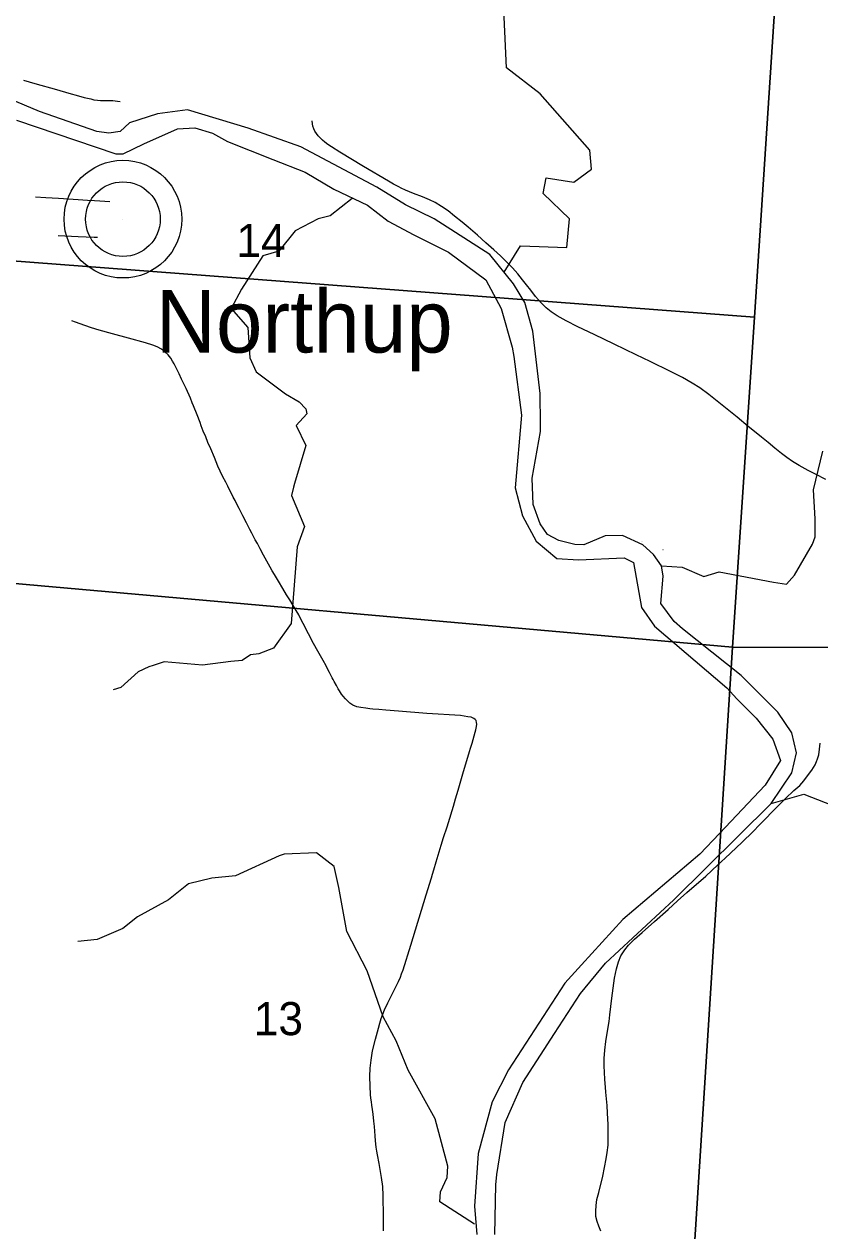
# Model space of a CAD drawing. Extents: x 0 to 34, y 0 to 22.
# Drawn here: x 24.476 to 25.483, y 16.271 to 17.797 of the extents above; entities that cross this region are included whole.
import ezdxf

# ---------------------------------------------------------------- set-up
doc = ezdxf.new("R2010")
doc.units = 0
for name, color, linetype in [('GM_X_County_Road', 7, 'Continuous'), ('GM_X_Major_River', 7, 'Continuous'), ('GM_X_Minor_River', 7, 'Continuous'), ('GM_X_Section', 7, 'Continuous'), ('GM_X_Section_Text', 7, 'Continuous'), ('GM_X_Township_Road', 7, 'Continuous'), ('GM_X_Unincorporated', 7, 'Continuous'), ('GM_X_Unincorporated_Location', 7, 'Continuous'), ('GM_X_Unincorporated_Text', 7, 'Continuous')]:
    doc.layers.add(name, color=color, linetype=linetype)

msp = doc.modelspace()

# ---------------------------------------------------------------- linework, layer by layer
at = {"layer": 'GM_X_County_Road'}
for points in [[(24.4755, 17.7258), (24.4898, 17.7216), (24.5169, 17.7139), (24.5328, 17.7094), (24.545, 17.7061), (24.5519, 17.7041), (24.5604, 17.7021), (24.5645, 17.7012), (24.5691, 17.7005), (24.5729, 17.7002), (24.576, 17.7001), (24.5819, 17.7), (24.5882, 17.7), (24.5912, 17.6998), (24.5942, 17.6995), (24.5976, 17.6989)], [(25.49, 17.2209), (25.4772, 17.2275), (25.4679, 17.2323), (25.4565, 17.2386), (25.4481, 17.2438), (25.4409, 17.2487), (25.434, 17.2539), (25.4257, 17.2605), (25.4171, 17.2675), (25.4089, 17.2743), (25.4, 17.2815), (25.392, 17.288), (25.3779, 17.2996), (25.3612, 17.3131), (25.3422, 17.3282), (25.3306, 17.3366), (25.3212, 17.3427), (25.3088, 17.3498), (25.2938, 17.3574), (25.2681, 17.3699), (25.2502, 17.3786), (25.2223, 17.3921), (25.1971, 17.4043), (25.1763, 17.4141), (25.1618, 17.4213), (25.1505, 17.4277), (25.1428, 17.4328), (25.1366, 17.4379), (25.1304, 17.4439), (25.1267, 17.4481), (25.123, 17.4523), (25.1168, 17.4602), (25.1115, 17.467), (25.1065, 17.4734), (25.1004, 17.4811), (25.0938, 17.4887), (25.086, 17.4967), (25.0788, 17.5035), (25.0701, 17.5115), (25.0603, 17.5203), (25.0497, 17.5297), (25.0379, 17.5398), (25.0302, 17.5462), (25.0206, 17.554), (25.0123, 17.5605), (25.0041, 17.5663), (24.9961, 17.5711), (24.9888, 17.5747), (24.9801, 17.5782), (24.9685, 17.5826), (24.9583, 17.5869), (24.9532, 17.5893), (24.95, 17.591), (24.9435, 17.5944), (24.9372, 17.598), (24.9052, 17.6165), (24.8755, 17.6349), (24.8648, 17.6415), (24.8602, 17.6446), (24.8565, 17.6474), (24.8535, 17.65), (24.8506, 17.6528), (24.8481, 17.6555), (24.8459, 17.6585), (24.844, 17.6614), (24.8426, 17.6643), (24.8415, 17.6675), (24.8409, 17.6706), (24.8404, 17.6743)], [(25.2056, 16.2704), (25.203, 16.2764), (25.2007, 16.2824), (25.1993, 16.2889), (25.1991, 16.2957), (25.1996, 16.3028), (25.2006, 16.3101), (25.2028, 16.3192), (25.2079, 16.34), (25.2102, 16.3507), (25.2124, 16.3618), (25.2136, 16.3699), (25.2146, 16.3789), (25.2148, 16.387), (25.215, 16.3951), (25.2149, 16.4051), (25.2141, 16.4193), (25.2135, 16.4293), (25.212, 16.446), (25.2115, 16.4522), (25.2106, 16.4621), (25.2102, 16.4713), (25.2097, 16.4788), (25.2099, 16.4887), (25.2106, 16.4992), (25.212, 16.5102), (25.2142, 16.5256), (25.2159, 16.5354), (25.217, 16.544), (25.2195, 16.565), (25.223, 16.5904), (25.2252, 16.6021), (25.2277, 16.6109), (25.231, 16.6186), (25.236, 16.626), (25.2407, 16.6319), (25.2483, 16.6396), (25.2576, 16.6478), (25.2732, 16.662), (25.2906, 16.6771), (25.3027, 16.6878), (25.3144, 16.6984), (25.3382, 16.719), (25.3535, 16.7335), (25.3627, 16.7418), (25.384, 16.7618), (25.3983, 16.7757), (25.4064, 16.7841), (25.4143, 16.7922), (25.422, 16.8003), (25.4307, 16.8091), (25.4389, 16.8173), (25.4497, 16.8274), (25.4572, 16.8338), (25.4623, 16.8396), (25.4671, 16.8461), (25.4722, 16.8533), (25.4765, 16.86), (25.4784, 16.864), (25.4797, 16.8675), (25.4811, 16.8728), (25.4822, 16.88), (25.4829, 16.8874)]]:
    msp.add_lwpolyline(points, dxfattribs=at)
at = {"layer": 'GM_X_Major_River'}
for points in [[(25.1294, 17.291), (25.1286, 17.3294), (25.1196, 17.4086), (25.1093, 17.4447), (25.0952, 17.4681), (25.0652, 17.5056), (24.9946, 17.5505), (24.9586, 17.5682), (24.9221, 17.5905), (24.8261, 17.6417), (24.7594, 17.665), (24.6828, 17.6882), (24.6449, 17.6832), (24.6094, 17.672), (24.5976, 17.661), (24.5833, 17.6587), (24.5681, 17.6609), (24.4957, 17.6864), (24.3895, 17.7308)], [(24.4665, 17.6753), (24.592, 17.6329), (24.6015, 17.6325), (24.6276, 17.6455), (24.67, 17.6643), (24.692, 17.6655), (24.7143, 17.6588), (24.7333, 17.6482), (24.7909, 17.6257), (24.8315, 17.6095), (24.868, 17.588), (24.9104, 17.5676), (24.9366, 17.5476), (24.9689, 17.5303), (25.0129, 17.5084), (25.0603, 17.4733), (25.0794, 17.4373), (25.0932, 17.3881), (25.0955, 17.3763), (25.1052, 17.3023), (25.0971, 17.2101), (25.1063, 17.1748), (25.1238, 17.1427), (25.15, 17.1211), (25.1773, 17.1193), (25.2349, 17.1218), (25.247, 17.1158), (25.257, 17.0589), (25.2734, 17.0354), (25.3649, 16.9572), (25.3774, 16.9436), (25.4021, 16.919), (25.423, 16.8925), (25.4326, 16.8656), (25.4133, 16.8344), (25.3556, 16.7731), (25.3306, 16.7472), (25.2335, 16.6645), (25.181, 16.607), (25.1599, 16.5838), (25.0886, 16.4743), (25.0682, 16.4336), (25.0506, 16.3683), (25.0459, 16.3018), (25.0486, 16.2662)], [(25.0714, 16.2662), (25.0727, 16.3289), (25.0738, 16.3418), (25.0846, 16.4078), (25.1068, 16.4584), (25.1468, 16.5204), (25.18, 16.5706), (25.2113, 16.609), (25.2978, 16.6894), (25.421, 16.8113), (25.447, 16.8497), (25.453, 16.8752), (25.4469, 16.9006), (25.4294, 16.9267), (25.383, 16.9728), (25.309, 17.0318), (25.2983, 17.0412), (25.2816, 17.0639), (25.2842, 17.0988), (25.2822, 17.1117), (25.2723, 17.1261), (25.2587, 17.1382), (25.2329, 17.1499), (25.2109, 17.1494), (25.184, 17.1383), (25.1727, 17.1387), (25.1526, 17.1439), (25.1382, 17.1514), (25.129, 17.1647), (25.1199, 17.1893), (25.1186, 17.2227), (25.1291, 17.2816), (25.1294, 17.291)]]:
    msp.add_lwpolyline(points, dxfattribs=at)
at = {"layer": 'GM_X_Minor_River'}
for points in [[(25.0831, 17.483), (25.1039, 17.5164), (25.1624, 17.5142), (25.1657, 17.5507), (25.1326, 17.5827), (25.1366, 17.6024), (25.1712, 17.5967), (25.1937, 17.6132), (25.1915, 17.6375), (25.1287, 17.7086), (25.0861, 17.7413), (25.0798, 17.8798)], [(24.8912, 17.5761), (24.8632, 17.5542), (24.848, 17.5504), (24.8188, 17.5355), (24.7983, 17.5096), (24.7779, 17.5039), (24.7509, 17.4617), (24.738, 17.4373), (24.7589, 17.413), (24.7615, 17.3746), (24.7698, 17.3571), (24.8066, 17.329), (24.824, 17.3192), (24.8324, 17.3104), (24.8335, 17.304), (24.8202, 17.2891), (24.8324, 17.2637), (24.8179, 17.2157), (24.8168, 17.2112), (24.8145, 17.2005), (24.8308, 17.1614), (24.8213, 17.1359), (24.8141, 17.0386), (24.7917, 17.0074), (24.7731, 17.0005), (24.7625, 16.9993), (24.7519, 16.9921), (24.7375, 16.9906), (24.7019, 16.986), (24.6533, 16.9901), (24.6393, 16.9855), (24.634, 16.984), (24.6203, 16.9775), (24.5984, 16.9577), (24.5889, 16.9547)], [(25.2822, 17.1117), (25.3084, 17.1098), (25.3357, 17.098), (25.355, 17.1041), (25.4237, 17.0909), (25.4403, 17.0886), (25.4506, 17.0997), (25.4733, 17.1389), (25.4767, 17.1484), (25.4764, 17.1712), (25.4745, 17.2077), (25.4863, 17.2567)], [(25.2574, 17.1426), (25.2574, 17.1426)], [(25.2579, 17.1424), (25.2578, 17.1424)], [(25.2842, 17.1318), (25.2841, 17.1319)], [(25.421, 16.8113), (25.4622, 16.8229), (25.5066, 16.8058), (25.5187, 16.796), (25.5607, 16.7249), (25.5698, 16.6975), (25.5804, 16.628), (25.5785, 16.5766), (25.58, 16.5226), (25.5694, 16.4835), (25.5606, 16.4302), (25.569, 16.3835), (25.5837, 16.32)], [(25.0458, 16.2789), (25.0018, 16.3072), (25.0026, 16.3198), (25.0113, 16.338), (25.0121, 16.3525), (24.9958, 16.4125), (24.9617, 16.4737), (24.9466, 16.511), (24.9303, 16.5414), (24.9098, 16.5995), (24.8841, 16.6493), (24.8742, 16.7048), (24.8682, 16.7314), (24.8458, 16.7489), (24.8049, 16.7469), (24.7988, 16.745), (24.7435, 16.7195), (24.7135, 16.7168), (24.6839, 16.7095), (24.6589, 16.6894), (24.6195, 16.6676), (24.6009, 16.6532), (24.5687, 16.6391), (24.544, 16.6364)]]:
    msp.add_lwpolyline(points, dxfattribs=at)
at = {"layer": 'GM_X_Section'}
for points in [[(25.4369, 18.0387), (25.9143, 18.0162), (26.4949, 18.0036), (26.4248, 16.9831), (25.8848, 17.0085), (25.3722, 17.0086), (25.3999, 17.4262), (25.4267, 17.8394)], [(25.4267, 17.8394), (25.3999, 17.4262), (24.3605, 17.505), (24.3871, 17.9146)], [(24.3605, 17.505), (25.3999, 17.4262), (25.3722, 17.0086), (24.3357, 17.1007)], [(24.3357, 17.1007), (25.3722, 17.0086), (25.3091, 16.0203), (24.2716, 16.0795)], [(26.4248, 16.9831), (26.3613, 15.9846), (25.3091, 16.0203), (25.3722, 17.0086), (25.8848, 17.0085)]]:
    msp.add_lwpolyline(points, close=True, dxfattribs=at)
at = {"layer": 'GM_X_Township_Road'}
for points in [[(24.4904, 17.5782), (24.5034, 17.5774), (24.5195, 17.5765), (24.5443, 17.5749), (24.5561, 17.5742), (24.5652, 17.5736), (24.5721, 17.5731), (24.5783, 17.5729), (24.5846, 17.5726)], [(24.5194, 17.5296), (24.5444, 17.5283), (24.5649, 17.5274), (24.5688, 17.5272)], [(25.0474, 16.9043), (25.0484, 16.9084), (25.0487, 16.9114), (25.0484, 16.9137), (25.0477, 16.9159), (25.0467, 16.9173), (25.0449, 16.9187), (25.0416, 16.9201), (25.0374, 16.9209), (25.0281, 16.9222), (24.9854, 16.9251), (24.9498, 16.928), (24.9338, 16.9292), (24.9247, 16.9299), (24.9173, 16.9305), (24.9135, 16.9309), (24.9082, 16.9315), (24.9019, 16.9325), (24.897, 16.9334), (24.8919, 16.9355), (24.888, 16.938), (24.8847, 16.9412), (24.8824, 16.9434), (24.8796, 16.9467), (24.8777, 16.9492), (24.8763, 16.9513), (24.875, 16.9534), (24.8735, 16.9561), (24.8711, 16.9604), (24.8684, 16.9653), (24.867, 16.968), (24.8658, 16.9702), (24.8624, 16.9767), (24.86, 16.9816), (24.858, 16.9854), (24.8545, 16.9919), (24.8527, 16.9951), (24.8493, 17.001), (24.8458, 17.0068), (24.8402, 17.0172), (24.8373, 17.0227), (24.8343, 17.0288), (24.8315, 17.0343), (24.8292, 17.0388), (24.8263, 17.0444), (24.8234, 17.0497), (24.8202, 17.0553), (24.8166, 17.0615), (24.8121, 17.0686), (24.808, 17.0751), (24.8032, 17.0831), (24.7977, 17.0921), (24.7939, 17.0985), (24.7926, 17.1007), (24.79, 17.1052), (24.7874, 17.1098), (24.7832, 17.1174), (24.779, 17.1251), (24.7747, 17.133), (24.7711, 17.1398), (24.7684, 17.1446), (24.764, 17.1528), (24.7615, 17.1578), (24.7572, 17.1661), (24.7529, 17.1749), (24.748, 17.1841), (24.7452, 17.1897), (24.743, 17.1941), (24.7407, 17.1985), (24.7393, 17.2013), (24.7365, 17.2068), (24.7337, 17.2123), (24.7311, 17.2175), (24.7276, 17.2244), (24.7241, 17.2313), (24.7213, 17.2377), (24.7168, 17.2487), (24.7121, 17.2596), (24.7087, 17.2675), (24.7058, 17.2747), (24.7028, 17.2819), (24.7002, 17.2888), (24.6986, 17.2929), (24.6948, 17.3028), (24.6904, 17.3138), (24.6888, 17.3178), (24.6864, 17.3235), (24.681, 17.336), (24.6754, 17.3476), (24.6721, 17.3545), (24.6685, 17.3619), (24.6658, 17.3673), (24.6637, 17.3707), (24.6616, 17.3741), (24.6583, 17.3785), (24.6543, 17.3823), (24.6499, 17.3855), (24.6445, 17.3885), (24.6388, 17.3908), (24.6298, 17.3935), (24.6082, 17.3996), (24.5878, 17.4051), (24.571, 17.4098), (24.5615, 17.4128), (24.553, 17.4156), (24.5411, 17.4199), (24.5363, 17.4215)], [(24.9307, 16.2705), (24.9306, 16.2785), (24.9305, 16.2885), (24.9303, 16.3152), (24.9297, 16.3269), (24.9283, 16.338), (24.9252, 16.3557), (24.9231, 16.3667), (24.9224, 16.3715), (24.9216, 16.3765), (24.9207, 16.3843), (24.9201, 16.3907), (24.9191, 16.4026), (24.9185, 16.4093), (24.9175, 16.4184), (24.9169, 16.4241), (24.9161, 16.4295), (24.9154, 16.4339), (24.9148, 16.4384), (24.9141, 16.4431), (24.9136, 16.4537), (24.9134, 16.4657), (24.9139, 16.4765), (24.9149, 16.4865), (24.9169, 16.4982), (24.9206, 16.5129), (24.9242, 16.5269), (24.9261, 16.5331), (24.9278, 16.539), (24.9299, 16.5445), (24.9321, 16.55), (24.9362, 16.559), (24.9476, 16.5818), (24.9495, 16.586), (24.952, 16.5914), (24.9536, 16.5957), (24.9554, 16.6007), (24.9654, 16.6321), (24.9847, 16.6957), (24.9912, 16.7171), (24.9927, 16.7218), (24.9942, 16.7271), (24.9972, 16.7373), (25.0037, 16.7586), (25.0067, 16.7681), (25.011, 16.7817), (25.0127, 16.787), (25.019, 16.8077), (25.0219, 16.8172), (25.0252, 16.8279), (25.0311, 16.8488), (25.0394, 16.8768), (25.0407, 16.881), (25.0426, 16.8875), (25.0466, 16.9012), (25.0474, 16.9043)]]:
    msp.add_lwpolyline(points, dxfattribs=at)
at = {"layer": 'GM_X_Unincorporated'}
for radius in [0.0744, 0.0472]:
    msp.add_circle((24.6011, 17.5501), radius, dxfattribs=at)
at = {"layer": 'GM_X_Unincorporated_Location'}
msp.add_line((24.6011, 17.5501), (24.6011, 17.5501), dxfattribs=at)

# ---------------------------------------------------------------- texts
at = {"layer": 'GM_X_Section_Text'}
for s, p in [('14', (24.7446, 17.5022)), ('13', (24.7666, 16.5181))]:
    msp.add_text(s, height=0.04186, rotation=0, dxfattribs=at).set_placement(p)
at = {"layer": 'GM_X_Unincorporated_Text'}
msp.add_text('Northup', height=0.07898, rotation=0, dxfattribs=at).set_placement((24.6425, 17.3814))

doc.saveas('drawing.dxf')
